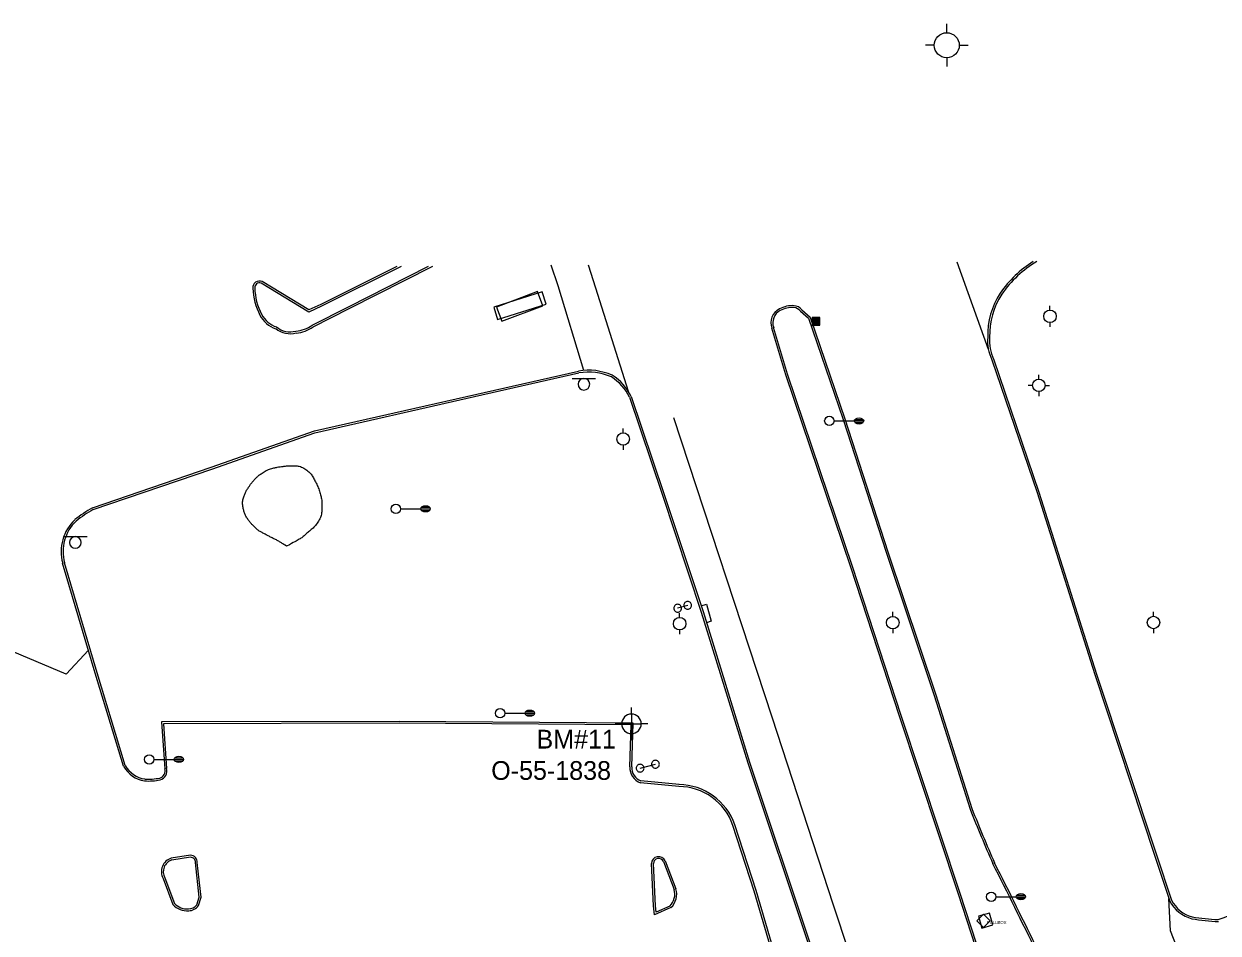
# Model space of a CAD drawing. Extents: x 2145380 to 2156929, y 139568 to 149130.
# Drawn here: x 2146909.9 to 2147292.3, y 143444.6 to 143735.7 of the extents above; entities that cross this region are included whole.
import ezdxf

# ---------------------------------------------------------------- set-up
doc = ezdxf.new("R2010")
doc.units = 0
for name, color, linetype in [('Default', 7, 'Continuous'), ('SURV_Benchmark', 7, 'Continuous'), ('SURV_Text', 7, 'Continuous'), ('TOPO_Asphalt', 7, 'Continuous'), ('TOPO_Concrete', 7, 'Continuous'), ('TOPO_Curb Back', 7, 'Continuous'), ('TOPO_DRAIN_Inlet Grate', 7, 'Continuous'), ('TOPO_Light Pole', 7, 'Continuous'), ('TOPO_Misc', 7, 'Continuous'), ('TOPO_Misc Line', 7, 'Continuous'), ('TOPO_Power Pole', 7, 'Continuous'), ('TOPO_Power Pullbox', 7, 'Continuous'), ('TOPO_Sign', 7, 'Continuous'), ('TOPO_Tree Line', 7, 'Continuous'), ('TOPO_Wall Freestanding', 7, 'Continuous'), ('TOPO_Water Fire Hydrant', 7, 'Continuous')]:
    doc.layers.add(name, color=color, linetype=linetype)

# ---------------------------------------------------------------- blocks, each defined once
blk = doc.blocks.new('POWPOL')
at = {"layer": 'TOPO_Power Pole'}
for p, q in [((0, 10.2), (0, 17.3)), ((0, -10.2), (0, -17.3))]:
    blk.add_line(p, q, dxfattribs=at)
blk.add_circle((0, 0), 10.2, dxfattribs=at)
blk = doc.blocks.new('FIRHYD')
at = {"layer": 'TOPO_Water Fire Hydrant'}
for p, q in [((-0.02, 10.16), (-0.03, 17.34)), ((10.16, 0.02), (17.34, 0.03)), ((-10.16, -0.02), (-17.34, -0.03)), ((0.02, -10.16), (0.03, -17.34))]:
    blk.add_line(p, q, dxfattribs=at)
blk.add_circle((0, 0), 10.16, dxfattribs=at)
blk = doc.blocks.new('CB')
at = {"layer": 'TOPO_Misc'}
for p, q in [((-3.08, 2.99), (3.24, 2.99)), ((-3.08, 2.68), (3.24, 2.68)), ((-3.08, 2.36), (3.24, 2.36)), ((-3.08, 2.05), (3.24, 2.05)), ((-3.08, 1.73), (3.24, 1.73)), ((-3.08, 1.4), (3.24, 1.4)), ((-3.08, 1.1), (3.24, 1.1)), ((-3.08, 0.77), (3.24, 0.77)), ((-3.08, 0.46), (3.24, 0.46)), ((-3.08, 0.14), (3.24, 0.14)), ((-3.08, -0.17), (3.24, -0.17)), ((-3.08, -0.48), (3.24, -0.48)), ((-3.08, -0.8), (3.24, -0.8)), ((-3.08, -1.11), (3.26, -1.11)), ((-3.08, -1.43), (3.26, -1.43)), ((-3.08, -1.75), (3.26, -1.75)), ((-3.08, -2.07), (3.26, -2.07)), ((-3.08, -2.39), (3.26, -2.39)), ((-3.08, -2.7), (3.26, -2.7)), ((-3.08, -3.02), (3.26, -3.02))]:
    blk.add_line(p, q, dxfattribs=at)
blk.add_lwpolyline([(3.26, -3.29), (3.24, 3.05), (-3.09, 3.04), (-3.08, -3.3), (3.26, -3.29)], dxfattribs=at)
blk = doc.blocks.new('LP')
at = {"layer": 'TOPO_Light Pole'}
blk.add_line((3.81, 0), (20.32, 0), dxfattribs=at)
for points in [[(20.32, 0), (27.94, 0)], [(20.32, 0), (23.5, 0)], [(20.83, 1.27), (27.43, 1.27)], [(20.83, 1.27), (23.5, 1.27)], [(23.71, 1.27), (27.43, 1.27)], [(23.71, 0), (27.94, 0)], [(20.83, -1.27), (27.43, -1.27)], [(20.83, -1.27), (23.5, -1.27)], [(23.71, -1.27), (27.43, -1.27)]]:
    blk.add_lwpolyline(points, dxfattribs=at)
blk.add_circle((0, 0), 3.81, dxfattribs=at)
blk.add_ellipse((24.13, 0), major_axis=(3.81, 0), ratio=0.666667, dxfattribs=at)
blk = doc.blocks.new('POST')
at = {"layer": 'TOPO_Misc'}
for start, end in [(89.99996, 180.00004), (179.99996, 270.00004), (359.99996, 90.00004), (269.99996, 0.00004)]:
    blk.add_arc((-0.01, 0.03), 3.16, start, end, dxfattribs=at)
blk = doc.blocks.new('pulbox')
at = {"layer": 'Default'}
blk.add_lwpolyline([(-5.38, -0.01), (-0.02, 5.42), (5.4, 0.06), (0.05, -5.36), (-5.38, -0.01)], dxfattribs=at)
blk.add_text('PULLBOX', height=2.54, dxfattribs=at).set_placement((2.54, -2.54))
blk = doc.blocks.new('BM')
at = {"layer": 'SURV_Benchmark'}
for p, q in [((0, 2.49), (0, 4.15)), ((-2.49, 0), (-4.16, 0)), ((4.16, 0), (2.49, 0)), ((0, -4.16), (0, -2.49))]:
    blk.add_line(p, q, dxfattribs=at)
for points in [[(-2.5, 0), (-2.49, 0), (0, 0), (0, -2.49), (0, -2.49)], [(-2.5, 0), (-2.49, 0), (0, 0), (0, -2.49), (0, -2.49)], [(0, 2.49), (0, 2.49), (0, 0), (2.49, 0), (2.49, 0), (2.49, 0)], [(0, 2.49), (0, 2.49), (0, 0), (2.49, 0), (2.49, 0), (2.49, 0), (2.49, 0)]]:
    blk.add_lwpolyline(points, dxfattribs=at)
for start, end in [(90.0638, 180.0068), (0.0638, 90.0068), (0.0638, 90.0068), (180.0638, 270.0068), (180.0638, 270.0068), (269.9472, 359.9927)]:
    blk.add_arc((0, 0), 2.5, start, end, dxfattribs=at)

msp = doc.modelspace()

# ---------------------------------------------------------------- linework, layer by layer
at = {"layer": 'TOPO_Asphalt'}
msp.add_line((2147218.76, 143631.41), (2147208.77, 143659.38), dxfattribs=at)
for points in [[(2147089.23, 143624.76), (2147081.01, 143651.78), (2147078.72, 143658.44)], [(2147090.55, 143658.55), (2147092.96, 143651.13), (2147103.4, 143618.09)], [(2146930.6, 143535.14), (2146923.4, 143527.56), (2146899.27, 143537.66)], [(2147294.01, 143402.05), (2147277.04, 143445.33), (2147276.56, 143455.65)]]:
    msp.add_lwpolyline(points, dxfattribs=at)
at = {"layer": 'TOPO_Concrete'}
msp.add_lwpolyline([(2147219.05, 143451.03), (2147215.56, 143450.01), (2147216.67, 143446.24), (2147220.15, 143447.26), (2147219.05, 143451.03)], dxfattribs=at)
at = {"layer": 'TOPO_Curb Back'}
for p, q in [((2147158.58, 143643.74), (2147161.17, 143641.44)), ((2147159.01, 143644.16), (2147161.69, 143641.79)), ((2147154.4, 143623.52), (2147149.97, 143638.44)), ((2147161.17, 143641.44), (2147172.23, 143609.01)), ((2147161.69, 143641.79), (2147172.8, 143609.2)), ((2147153.83, 143623.34), (2147149.4, 143638.25)), ((2147174.64, 143561.81), (2147153.83, 143623.34)), ((2147175.21, 143562), (2147154.4, 143623.52)), ((2147172.23, 143609.01), (2147185.99, 143566.52)), ((2147172.8, 143609.2), (2147186.56, 143566.71)), ((2147185.99, 143566.52), (2147201.34, 143520.66)), ((2147186.56, 143566.71), (2147201.91, 143520.85)), ((2147190.82, 143514.24), (2147175.21, 143562)), ((2147190.25, 143514.05), (2147174.64, 143561.81)), ((2147201.34, 143520.66), (2147212.9, 143484.26)), ((2147201.91, 143520.85), (2147213.46, 143484.46)), ((2147209.17, 143457.11), (2147190.25, 143514.05)), ((2147209.74, 143457.3), (2147190.82, 143514.24)), ((2146963.26, 143469.52), (2146957.1, 143468.61)), ((2146963.29, 143468.92), (2146957.24, 143468.02)), ((2146966.02, 143456.14), (2146964.82, 143467.23)), ((2146966.63, 143456.08), (2146965.43, 143467.25)), ((2147111.52, 143453.34), (2147110.85, 143466.87)), ((2147112.12, 143453.38), (2147111.45, 143466.88)), ((2147114.7, 143467.53), (2147118.11, 143458.6)), ((2147115.25, 143467.77), (2147118.67, 143458.79)), ((2146954.46, 143462.09), (2146957.57, 143453.8)), ((2146955.01, 143462.34), (2146958.09, 143454.12)), ((2146965.24, 143453.7), (2146966.02, 143456.14)), ((2146965.78, 143453.42), (2146966.63, 143456.08)), ((2147222.83, 143415.37), (2147209.17, 143457.11)), ((2147223.4, 143415.56), (2147209.74, 143457.3)), ((2147111.84, 143450.45), (2147111.52, 143453.34)), ((2147117.1, 143452.79), (2147111.84, 143450.45)), ((2147112.34, 143451.34), (2147112.12, 143453.38)), ((2147116.76, 143453.3), (2147112.34, 143451.34))]:
    msp.add_line(p, q, dxfattribs=at)
for points in [[(2147030.68, 143657.98), (2147005.21, 143645.27), (2147001.09, 143643.41), (2146985.88, 143652.65)], [(2147029.31, 143657.97), (2147004.95, 143645.81), (2147001.13, 143644.09), (2146986.15, 143653.19)], [(2147002.17, 143639.25), (2147013.8, 143645.12), (2147039.46, 143658.07)], [(2147002.49, 143638.73), (2147014.07, 143644.59), (2147040.81, 143658.08)], [(2147219.85, 143628.17), (2147234.36, 143585.63), (2147252.82, 143527.37), (2147271.97, 143469.53), (2147276.81, 143454.88)], [(2147220.41, 143628.4), (2147234.93, 143585.82), (2147253.39, 143527.55), (2147272.54, 143469.72), (2147277.37, 143455.12)], [(2146931.88, 143580.74), (2146969.87, 143593.74), (2147002.94, 143605.38), (2147051.67, 143616.42), (2147087.51, 143624.51)], [(2146932.12, 143580.19), (2146970.07, 143593.18), (2147003.11, 143604.8), (2147051.81, 143615.83), (2147087.62, 143623.92)], [(2147103.78, 143616.14), (2147114.24, 143585.18), (2147126.8, 143547.4), (2147141.7, 143499.15), (2147161.24, 143440.63), (2147180.64, 143382.35), (2147196.74, 143332.44), (2147212.6, 143285.35), (2147225.45, 143246.61), (2147229.49, 143234.16)], [(2147104.33, 143616.36), (2147114.81, 143585.37), (2147127.37, 143547.58), (2147142.27, 143499.34), (2147161.81, 143440.82), (2147181.21, 143382.54), (2147197.31, 143332.63), (2147213.16, 143285.54), (2147226.02, 143246.79), (2147230.07, 143234.33)], [(2146941.81, 143498.04), (2146932.77, 143527.82), (2146922.31, 143563.02)], [(2146942.37, 143498.27), (2146933.35, 143527.99), (2146922.89, 143563.19)], [(2147104.53, 143497.86), (2147104.98, 143511.85), (2147030.09, 143512.41), (2146953.93, 143512.25), (2146954.98, 143497.25)], [(2147103.93, 143497.88), (2147104.36, 143511.25), (2147030.09, 143511.81), (2146954.57, 143511.65), (2146955.58, 143497.36)], [(2147119.67, 143492.17), (2147107.46, 143493.33)], [(2147119.63, 143491.57), (2147107.32, 143492.74)], [(2147167.49, 143264.93), (2147164.49, 143319.81), (2147161.9, 143366.93), (2147159.96, 143402.77), (2147143.75, 143458.08), (2147136.94, 143479.1)], [(2147168.09, 143264.97), (2147165.09, 143319.84), (2147162.5, 143366.96), (2147160.55, 143402.87), (2147144.33, 143458.26), (2147137.51, 143479.29)]]:
    msp.add_lwpolyline(points, dxfattribs=at)
for centre, radius, start, end in [((2147252.83, 143628.46), 36.89, 122.414, 145.2359), ((2147252.83, 143628.46), 36.29, 120.8506, 145.2231), ((2146985.33, 143651.26), 2.1, 67.1747, 186.5601), ((2147001.57, 143651.25), 18.32, 180.7114, 208.6516), ((2146985.33, 143651.26), 1.5, 68.7317, 187.6446), ((2147001.57, 143651.25), 17.72, 180.6047, 208.6831), ((2147243.01, 143636.07), 24.48, 146.7763, 181.6798), ((2147243.01, 143636.07), 23.88, 146.7956, 181.7651), ((2146993.32, 143646.42), 8.77, 206.8119, 251.4706), ((2146993.32, 143646.42), 8.17, 206.7449, 252.2168), ((2147154.08, 143639.99), 4.98, 116.7158, 200.448), ((2147154.08, 143639.99), 4.38, 116.6644, 200.7072), ((2147156.03, 143636.37), 9.1, 86.8889, 117.478), ((2147156.03, 143636.37), 8.5, 86.9973, 117.5053), ((2147156.12, 143641.64), 3.24, 40.4853, 83.6255), ((2147156.12, 143641.64), 3.84, 41.1266, 83.8956), ((2146995.19, 143643.95), 6.87, 230.5616, 285.1288), ((2146996.33, 143646.99), 9.7, 273.8383, 307.0133), ((2146996.33, 143646.99), 10.3, 274.1661, 306.7112), ((2146995.19, 143643.95), 7.47, 231.4433, 284.6714), ((2147232.21, 143634.14), 13.73, 174.9278, 205.8085), ((2147232.21, 143634.14), 13.13, 174.774, 205.9664), ((2147090.77, 143606.41), 18.39, 65.8122, 100.2223), ((2147090.77, 143606.41), 17.79, 65.9442, 100.1804), ((2147089.83, 143609.62), 16, 24.9268, 58.0041), ((2147089.83, 143609.62), 15.4, 25.0476, 57.8519), ((2146949.48, 143548.26), 36.94, 118.4475, 129.002), ((2146949.48, 143548.26), 36.34, 118.5263, 128.9649), ((2146935.93, 143566.72), 14.11, 133.4553, 195.1941), ((2146935.93, 143566.72), 13.51, 133.5535, 195.1644), ((2146949.85, 143502.42), 9.15, 208.5768, 261.7222), ((2146949.85, 143502.42), 8.55, 208.9815, 261.5689), ((2146952.79, 143496.5), 2.32, 285.7266, 18.8274), ((2146952.79, 143496.5), 2.92, 285.2185, 17.213), ((2147109.19, 143497.66), 5.27, 177.6129, 249.182), ((2147109.19, 143497.66), 4.67, 177.5791, 248.2173), ((2146949.84, 143512.65), 19.34, 266.1282, 281.0865), ((2146949.84, 143512.65), 18.74, 266.1994, 281.017), ((2147119.4, 143472.99), 18.58, 19.1922, 89.2797), ((2147119.4, 143472.99), 19.18, 19.1727, 89.2053), ((2147747, 143696.82), 574.85, 201.70163, 203.58229), ((2147747, 143696.82), 574.25, 201.70376, 203.58047), ((2146958.48, 143464.26), 4.57, 107.6472, 208.2544), ((2146958.48, 143464.26), 3.97, 108.3207, 208.8153), ((2146963.22, 143467.31), 2.21, 358.4008, 88.9348), ((2146963.22, 143467.31), 1.61, 357.0711, 87.3013), ((2147113.16, 143466.8), 2.31, 24.7151, 178.2287), ((2147113.16, 143466.8), 1.71, 25.3371, 177.4816), ((2146150.75, 142920.35), 1200.96, 25.5697, 27.06794), ((2146150.75, 142920.35), 1201.56, 25.5696, 27.06707), ((2147113.02, 143457.07), 5.91, 313.6232, 16.9216), ((2147113.02, 143457.07), 5.31, 314.7158, 16.7032), ((2147286.97, 143460.32), 10.92, 208.446, 254.2795), ((2146962.21, 143458.02), 6.27, 222.2905, 274.3111), ((2146962.21, 143458.02), 5.67, 223.4244, 274.3593), ((2146962.44, 143455.93), 3.58, 273.3375, 321.4347), ((2146962.44, 143455.93), 4.18, 273.4118, 323.001), ((2147286.97, 143460.32), 11.52, 208.1768, 254.4566), ((2147296.35, 143527.68), 79.45, 260.9739, 267.1385), ((2147296.35, 143527.68), 78.85, 260.999, 267.057), ((2147276.24, 143497.18), 50.84, 288.4111, 294.7559)]:
    msp.add_arc(centre, radius, start, end, dxfattribs=at)
at = {"layer": 'TOPO_DRAIN_Inlet Grate'}
msp.add_lwpolyline([(2147126.79, 143549.34), (2147128.45, 143549.91), (2147130.02, 143544.47), (2147128.48, 143543.99)], dxfattribs=at)
at = {"layer": 'TOPO_Misc Line'}
msp.add_lwpolyline([(2147242.33, 143232.97), (2147210.41, 143329.68), (2147184.07, 143408.45), (2147169.19, 143453.56), (2147149.47, 143513.78), (2147117.99, 143609.55)], dxfattribs=at)
at = {"layer": 'TOPO_Sign'}
msp.add_lwpolyline([(2147061.59, 143641.05), (2147077.08, 143645.92), (2147075.85, 143649.85), (2147060.36, 143644.99)], close=True, dxfattribs=at)
for points in [[(2147085.46, 143622.18), (2147092.95, 143622.19)], [(2147087.34, 143620.32), (2147087.34, 143620.32)], [(2147089.21, 143622.18), (2147089.21, 143622.18)], [(2147091.08, 143620.32), (2147091.08, 143620.32)], [(2147089.21, 143618.45), (2147089.21, 143618.45)], [(2146922.62, 143571.53), (2146930.12, 143571.54)], [(2146924.51, 143569.66), (2146924.51, 143569.66)], [(2146926.37, 143571.53), (2146926.37, 143571.53)], [(2146928.24, 143569.66), (2146928.24, 143569.66)], [(2146926.37, 143567.8), (2146926.37, 143567.8)], [(2147122.45, 143549.51), (2147119.23, 143548.61)], [(2147107.22, 143497.41), (2147112.13, 143498.68)]]:
    msp.add_lwpolyline(points, dxfattribs=at)
for centre, start, end in [((2147089.21, 143620.32), 90, 180), ((2147089.21, 143620.32), 180, 270), ((2147089.21, 143620.32), 360, 90), ((2147089.21, 143620.32), 270, 0), ((2146926.37, 143569.66), 90, 180), ((2146926.37, 143569.66), 180, 270), ((2146926.37, 143569.66), 360, 90), ((2146926.37, 143569.66), 270, 0)]:
    msp.add_arc(centre, 1.87, start, end, dxfattribs=at)
at = {"layer": 'TOPO_Tree Line'}
msp.add_open_spline([(2146994.02, 143568.44), (2146995.38, 143569.21), (2146996.74, 143569.97), (2146998.1, 143570.73), (2146999.17, 143571.33), (2147000.04, 143572.19), (2147000.98, 143572.99), (2147002.21, 143574.05), (2147003.31, 143575.05), (2147004.23, 143576.54), (2147005.1, 143577.97), (2147005.31, 143579.48), (2147005.34, 143580.99), (2147005.36, 143582.28), (2147005.24, 143583.59), (2147004.89, 143584.88), (2147004.46, 143586.48), (2147003.86, 143587.94), (2147003.08, 143589.43), (2147002.41, 143590.71), (2147001.74, 143591.82), (2147000.49, 143592.76), (2146999.16, 143593.75), (2146997.73, 143594.19), (2146996.23, 143594.22), (2146995.11, 143594.23), (2146993.98, 143594.16), (2146992.87, 143594.03), (2146991.91, 143593.91), (2146990.97, 143593.78), (2146990.03, 143593.55), (2146988.52, 143593.18), (2146987.13, 143592.54), (2146985.83, 143591.64), (2146984.93, 143591.01), (2146984.19, 143590.3), (2146983.48, 143589.49), (2146982.87, 143588.81), (2146982.35, 143588.11), (2146981.84, 143587.35), (2146981.2, 143586.39), (2146980.72, 143585.38), (2146980.35, 143584.31), (2146979.91, 143583.01), (2146979.9, 143581.55), (2146980.22, 143580.24), (2146980.5, 143579.11), (2146980.94, 143578.02), (2146981.64, 143577.03), (2146982.19, 143576.26), (2146982.76, 143575.61), (2146983.43, 143574.97), (2146984.15, 143574.29), (2146984.84, 143573.56), (2146985.71, 143573.09), (2146986.69, 143572.55), (2146987.67, 143572.03), (2146988.65, 143571.51), (2146989.68, 143570.96), (2146990.76, 143570.5), (2146991.75, 143569.87), (2146992.5, 143569.4), (2146993.26, 143568.92), (2146994.02, 143568.44)], degree=3, dxfattribs=at)
at = {"layer": 'TOPO_Wall Freestanding'}
msp.add_lwpolyline([(2147062.93, 143640.48), (2147076.05, 143645.4), (2147074.35, 143649.95), (2147061.22, 143645.03)], close=True, dxfattribs=at)

# ---------------------------------------------------------------- block references
at = {"layer": 'SURV_Benchmark', "xscale": 1.25, "yscale": 1.25}
msp.add_blockref('BM', (2147104.44, 143511.6), dxfattribs=at)
at = {"layer": 'TOPO_Light Pole', "xscale": 0.39370000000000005, "yscale": 0.3937000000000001}
for p in [(2147167.81, 143608.58), (2147029.01, 143580.43), (2147062.37, 143515.02), (2146950.02, 143500.21), (2147219.66, 143456.27)]:
    msp.add_blockref('LP', p, dxfattribs=at)
at = {"layer": 'TOPO_Misc', "xscale": 0.39370000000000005, "yscale": 0.3937000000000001}
for name, p in [('CB', (2147163.53, 143640.47)), ('POST', (2147122.45, 143549.51)), ('POST', (2147119.23, 143548.61)), ('POST', (2147107.22, 143497.41)), ('POST', (2147112.13, 143498.68))]:
    msp.add_blockref(name, p, dxfattribs=at)
at = {"layer": 'TOPO_Power Pole', "xscale": 0.19685000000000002, "yscale": 0.19685000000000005}
for p in [(2147238.45, 143642.06), (2147101.8, 143602.77), (2147119.88, 143543.67), (2147188.12, 143544.01), (2147271.59, 143544.05)]:
    msp.add_blockref('POWPOL', p, dxfattribs=at)
at = {"layer": 'TOPO_Power Pullbox', "xscale": 0.39370000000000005, "yscale": 0.3937000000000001}
msp.add_blockref('pulbox', (2147217.18, 143448.53), dxfattribs=at)
at = {"layer": 'TOPO_Water Fire Hydrant'}
for p, xscale, yscale in [((2147205.42, 143728.84), 0.39370000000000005, 0.3937000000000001), ((2147234.89, 143619.95), 0.19685000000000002, 0.19685000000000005)]:
    msp.add_blockref('FIRHYD', p, dxfattribs=dict(at, xscale=xscale, yscale=yscale))

# ---------------------------------------------------------------- texts
at = {"layer": 'SURV_Text'}
for s, p in [('BM#11', (2147074.03, 143503.71)), ('O-55-1838', (2147059.54, 143493.68))]:
    msp.add_text(s, height=6, dxfattribs=at).set_placement(p)

doc.saveas('drawing.dxf')
